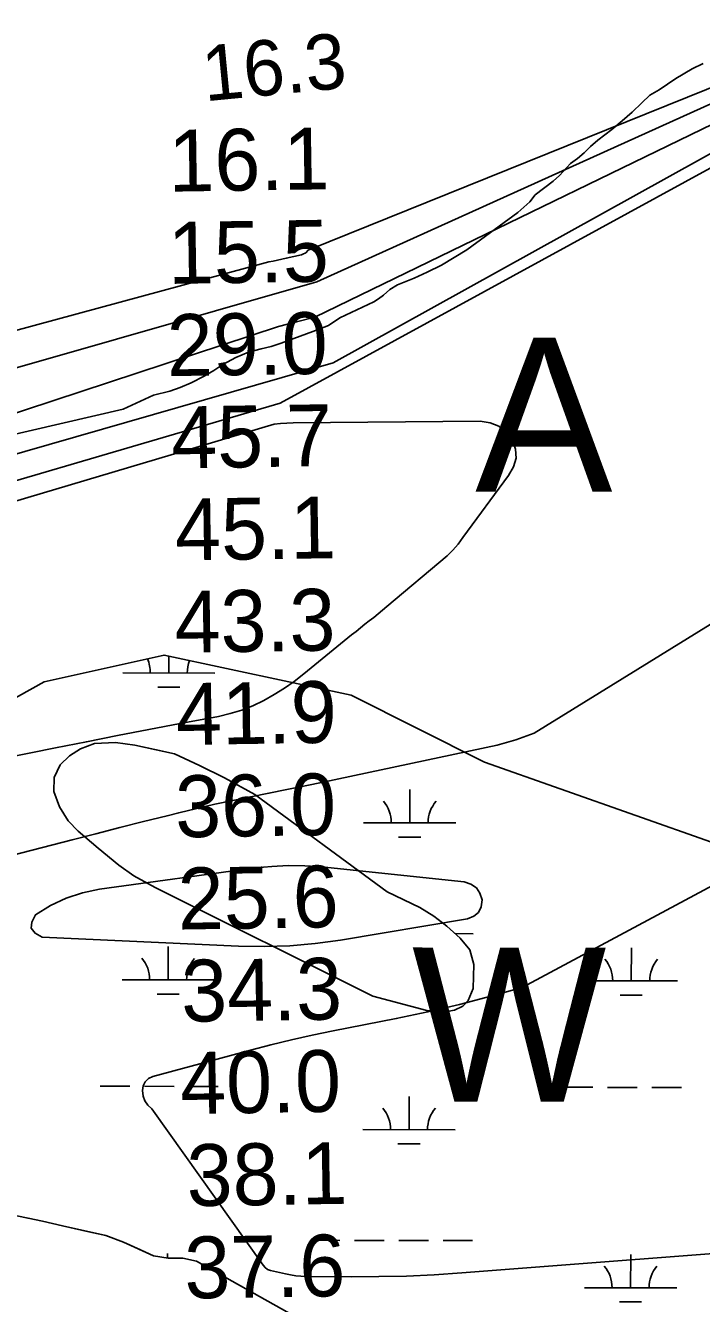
# Model space of a CAD drawing. Extents: x 3219052 to 3256913, y 800770 to 826146.
# Drawn here: x 3231079 to 3231811, y 813685 to 815070 of the extents above; entities that cross this region are included whole.
import ezdxf

# ---------------------------------------------------------------- set-up
doc = ezdxf.new("R2010")
doc.units = 0
for name, color, linetype in [('V-RIVR-IDEN', 7, 'Continuous'), ('V-RIVR-RANG', 7, 'Continuous'), ('V-SITE-VEGE', 7, 'Continuous'), ('V-TOPO-DPTH', 7, 'Continuous'), ('V-TOPO-MAJR', 7, 'Continuous'), ('V-TOPO-MINR', 7, 'Continuous'), ('V-TOPO-SHOR', 7, 'Continuous'), ('V-WETL-SWMP', 7, 'Continuous')]:
    doc.layers.add(name, color=color, linetype=linetype)

msp = doc.modelspace()

# ---------------------------------------------------------------- linework, layer by layer
at = {"layer": 'V-SITE-VEGE'}
for points in [[(3231746.5, 814986.4), (3231755.4, 814994.8), (3231765.5, 815000.8), (3231783.5, 815013), (3231801.4, 815023.4), (3231813.1, 815029.3)], [(3231051.7, 814623.6), (3231184.3, 814654.4), (3231217.2, 814669.8), (3231235.1, 814673.9), (3231246.4, 814677.8), (3231258.2, 814683.1), (3231272.2, 814690.1), (3231282.9, 814696.5), (3231292.5, 814702.9), (3231306.7, 814710.5), (3231320.5, 814716.2), (3231334.2, 814719.7), (3231344.8, 814722.5), (3231355.7, 814726.1), (3231390, 814738.8), (3231407.1, 814745.3), (3231419.4, 814753.4), (3231456.3, 814770.7), (3231461.4, 814773.9), (3231466.5, 814778.2), (3231473.5, 814784.3), (3231481.9, 814789.2), (3231499.9, 814796.5), (3231514.1, 814803.1), (3231529.5, 814810.4), (3231557.1, 814827.3), (3231612.3, 814867.6), (3231625.3, 814879.4), (3231631.1, 814886.8), (3231650.4, 814901.8), (3231657.5, 814907.6), (3231669.5, 814920.8), (3231677, 814926.2), (3231684, 814932.4), (3231691.2, 814939.1), (3231699, 814946.2), (3231714, 814957.8), (3231725.2, 814967.2), (3231736.1, 814976.3), (3231746.5, 814986.4)], [(3231370.8, 813670.7), (3231263.9, 813730.8), (3231249, 813734.1), (3231233.3, 813734), (3231217.5, 813736.5), (3231184.8, 813751.3), (3231165.6, 813758.7), (3231118.7, 813769.3), (3231097, 813774.3), (3231081.4, 813777.3), (3230918.1, 813810.9)]]:
    msp.add_lwpolyline(points, dxfattribs=at)
msp.add_lwpolyline([(3231455.1, 814018.2), (3231513.8, 814002.7), (3231524.4, 814001.6), (3231533.4, 814001.2), (3231543.5, 814002.8), (3231552.6, 814007.4), (3231558.5, 814013.3), (3231563.8, 814026.6), (3231564.5, 814052.3), (3231560.2, 814068.5), (3231549.7, 814081), (3231535.2, 814094.1), (3231521.3, 814104.9), (3231506.1, 814114.2), (3231470.6, 814131.4), (3231327.2, 814236.6), (3231294.3, 814254.9), (3231267.3, 814268.2), (3231240, 814280.8), (3231197.3, 814290.1), (3231176, 814293.1), (3231153.5, 814292), (3231138.2, 814286.2), (3231126.4, 814278.7), (3231116.3, 814269), (3231109.6, 814255), (3231109.3, 814240.1), (3231115.6, 814223.4), (3231125, 814208.1), (3231135.8, 814197.1), (3231157.4, 814178.6), (3231179.7, 814160.3), (3231196.2, 814148.5), (3231219.1, 814136)], close=True, dxfattribs=at)
at = {"layer": 'V-TOPO-DPTH'}
msp.add_lwpolyline([(3229216.4, 814641), (3229973.1, 814420.4), (3229979.2, 814421), (3229985.2, 814421.8), (3229991.3, 814422.6), (3230023.5, 814427.6), (3230041.5, 814430.8), (3230672.1, 814632.5), (3231342.2, 814814.2), (3231347, 814815), (3231351.7, 814816), (3231356.4, 814817), (3231361.2, 814818), (3231377.7, 814821.9), (3231379.4, 814822.4), (3231382.5, 814824.1), (3231385, 814826.7), (3231968.2, 815062.1)], dxfattribs=at)
at = {"layer": 'V-TOPO-MAJR'}
for points in [[(3229239.8, 814015.9), (3230018.6, 814365.6), (3230054.4, 814372.1), (3230249.6, 814407.6), (3230321.4, 814421), (3230393.2, 814434.6), (3230464.8, 814448.7), (3230536.4, 814463.2), (3230638.5, 814484.1), (3230659, 814488.4), (3231412, 814704.6), (3231956.2, 815006.5), (3231977.2, 815008.9), (3231998.3, 815011.3), (3232019.3, 815013.7), (3232638.1, 815145.4), (3232645.8, 815145.8), (3232653.6, 815146.2), (3232661.3, 815146.5), (3232669.1, 815146.7), (3232929.4, 815153.5), (3233006.6, 815155.4), (3233083.7, 815157.2)], [(3231122.6, 814124.5), (3231105.8, 814116.3), (3231089.6, 814106.4), (3231085.4, 814098.5), (3231084.6, 814091.7), (3231089, 814086.4), (3231096.8, 814082.1), (3231309.4, 814072.4), (3231337.2, 814072), (3231365, 814072.8), (3231392.6, 814075.3), (3231420.1, 814079), (3231557.7, 814101.8), (3231564.5, 814104.8), (3231569.7, 814109), (3231572.4, 814115.1), (3231573.5, 814122.4), (3231571.1, 814129.7), (3231567.4, 814135.6), (3231561.5, 814139.4), (3231554.2, 814141.9), (3231399.6, 814158.2), (3231381.5, 814159.4), (3231363.5, 814159.8), (3231345.5, 814158.8), (3231327.5, 814157.1), (3231159, 814134.1), (3231140.5, 814130.2), (3231122.6, 814124.5)]]:
    msp.add_lwpolyline(points, dxfattribs=at)
at = {"layer": 'V-TOPO-MINR'}
for points in [[(3229272.3, 814142.3), (3229994.7, 814406), (3230009.2, 814408.3), (3230073.9, 814418.5), (3230120.6, 814426.7), (3230167.1, 814435.8), (3230213.3, 814446.4), (3230259.3, 814458), (3230329.7, 814476.9), (3230630.3, 814574), (3231394.5, 814792.5), (3231945.4, 815041.4), (3231978, 815045.1), (3232010.6, 815048.8), (3232612.4, 815170.6), (3232633.9, 815172.1), (3232655.5, 815173.5), (3232677, 815174.6), (3232698.5, 815175.7), (3233370.6, 815232.4)], [(3229216.4, 814641), (3229973.1, 814420.4), (3229979.2, 814421), (3229985.2, 814421.8), (3229991.3, 814422.6), (3230023.5, 814427.6), (3230041.5, 814430.8), (3230672.1, 814632.5), (3231342.2, 814814.2), (3231347, 814815), (3231351.7, 814816), (3231356.4, 814817), (3231361.2, 814818), (3231377.7, 814821.9), (3231379.4, 814822.4), (3231382.5, 814824.1), (3231385, 814826.7), (3231968.2, 815062.1)], [(3229228, 814067.2), (3230005.8, 814387.7), (3230030.2, 814391.8), (3230129.4, 814408.6), (3230203.2, 814421.7), (3230678.2, 814523.5), (3230683.5, 814524.8), (3230688.7, 814526.1), (3230707.2, 814530.8), (3230713.1, 814532.4), (3230718.9, 814534.2), (3230724.6, 814536.2), (3230730.2, 814538.4), (3230735.8, 814540.6), (3230741.4, 814542.9), (3231352.9, 814744.1), (3231372.5, 814749), (3231392.1, 814754.1), (3231947.6, 815023.6)], [(3230714.2, 814473.1), (3231354.6, 814660.8), (3231952.8, 814988)], [(3230702.1, 814445.9), (3231348.1, 814638.1), (3231354.9, 814638.9), (3231361.8, 814639.3), (3231368.8, 814639.6), (3231571.5, 814641.4), (3231582.2, 814639.7), (3231591.8, 814636), (3231599.7, 814629.5), (3231606.5, 814621), (3231609.7, 814611), (3231610.5, 814601.2), (3231607.6, 814591.8), (3231602.3, 814582.7), (3231552.5, 814515.5), (3231547.7, 814508.2), (3231541.9, 814501.6), (3231535.5, 814495.5), (3231470.4, 814440.5), (3231465.7, 814436.5), (3231460.9, 814432.6), (3231456.1, 814428.8), (3231451.3, 814425), (3231446.5, 814421.3), (3231441.6, 814417.5), (3231436.9, 814413.6), (3231432.1, 814409.8), (3231380.4, 814367.4), (3231370, 814359.4), (3231359.4, 814351.9), (3231348.3, 814345), (3231336.9, 814338.5), (3231325.1, 814332.9), (3231313.1, 814328.1), (3231300.6, 814324.4), (3231287.9, 814321.4), (3231246.1, 814313.6), (3231212.3, 814307.1), (3231178.5, 814300.7)], [(3231891.5, 814464.6), (3231629.8, 814303.1), (3231610.1, 814295.9), (3231589.7, 814290.2), (3231401.1, 814250.2), (3231381.6, 814246.1), (3231362, 814242.1), (3231342.4, 814238.1), (3231322.8, 814234.3), (3231303.2, 814230.3), (3231283.7, 814226.2), (3231264.2, 814221.7), (3231244.8, 814217), (3231232.1, 814213.8), (3231206.4, 814207.3), (3231180.7, 814200.8), (3231155, 814194.2), (3231129.3, 814187.7), (3231019.6, 814159.5)], [(3231178.5, 814300.7), (3231144.7, 814294), (3231111, 814287.3), (3230912.6, 814247.4)], [(3231932.5, 813747.6), (3231551.6, 813718.1), (3231521.7, 813716.2), (3231491.7, 813714.7), (3231461.7, 813714.1), (3231431.6, 813713.9), (3231382.8, 813714.3), (3231377.2, 813714.6), (3231371.6, 813715), (3231366, 813715.9), (3231360.5, 813717), (3231344.2, 813720.7), (3231341, 813721.9), (3231338.3, 813723.9), (3231336.2, 813726.5), (3231215.4, 813895.9), (3231211.3, 813900), (3231208.1, 813904.6), (3231206.3, 813909.9), (3231205.3, 813915.7), (3231206.3, 813920.9), (3231208.3, 813925.4), (3231212, 813928.7), (3231216.7, 813931.1), (3231322.5, 813959.7), (3231344.7, 813965.5), (3231367.1, 813970.9), (3231389.5, 813975.9), (3231412.1, 813980.5), (3231480.4, 813993.9), (3231514.8, 814001.1), (3231549, 814009.1), (3231583, 814018), (3231616.8, 814027.6), (3231960.3, 814211.4)]]:
    msp.add_lwpolyline(points, dxfattribs=at)
at = {"layer": 'V-TOPO-SHOR'}
for points in [[(3231455.1, 814018.2), (3231219.1, 814136), (3231196.2, 814148.5), (3231179.7, 814160.3), (3231157.4, 814178.6), (3231135.8, 814197.1), (3231125, 814208.1), (3231115.6, 814223.4), (3231109.3, 814240.1), (3231109.6, 814255), (3231116.3, 814269), (3231126.4, 814278.7), (3231138.2, 814286.2), (3231153.5, 814292), (3231176, 814293.1), (3231197.3, 814290.1), (3231218.7, 814285.4), (3231240, 814280.8), (3231267.3, 814268.2), (3231294.3, 814254.9), (3231327.2, 814236.6), (3231470.6, 814131.4), (3231506.1, 814114.2), (3231521.3, 814104.9), (3231535.2, 814094.1), (3231549.7, 814081), (3231560.2, 814068.5), (3231564.5, 814052.3), (3231563.8, 814026.6), (3231558.5, 814013.3), (3231552.6, 814007.4), (3231543.5, 814002.8), (3231533.4, 814001.2), (3231524.4, 814001.6), (3231513.8, 814002.7), (3231455.1, 814018.2)], [(3230918.1, 813810.9), (3231081.4, 813777.3), (3231097, 813774.3), (3231118.7, 813769.3), (3231144.1, 813763.5), (3231165.6, 813758.7), (3231184.8, 813751.3), (3231203.1, 813743), (3231217.5, 813736.5), (3231233.3, 813734), (3231249, 813734.1), (3231263.9, 813730.8), (3231370.8, 813670.7)]]:
    msp.add_lwpolyline(points, dxfattribs=at)
at = {"layer": 'V-WETL-SWMP'}
for p, q in [((3231234, 814368.4), (3231234, 814386.7)), ((3231184, 814368.5), (3231284, 814368.3)), ((3231221.9, 814353), (3231245.9, 814353)), ((3231495.1, 814206), (3231495.1, 814242)), ((3231445.1, 814206.1), (3231545.1, 814205.9)), ((3231483, 814190.6), (3231507, 814190.6)), ((3231544.3, 814085.9), (3231564, 814085.8)), ((3231233.3, 814035.8), (3231233.3, 814071.8)), ((3231735.2, 814034.7), (3231735.3, 814070.7)), ((3231183.3, 814035.9), (3231283.3, 814035.7)), ((3231685.2, 814034.8), (3231785.2, 814034.6)), ((3231221.2, 814020.4), (3231245.2, 814020.3)), ((3231723.1, 814019.3), (3231747.1, 814019.3)), ((3231159.6, 813920.5), (3231191.6, 813920.4)), ((3231207.6, 813920.4), (3231239.6, 813920.3)), ((3231255.6, 813920.3), (3231287.6, 813920.2)), ((3231661.5, 813919.4), (3231693.5, 813919.4)), ((3231709.5, 813919.3), (3231741.5, 813919.3)), ((3231757.5, 813919.2), (3231789.5, 813919.2)), ((3231494.4, 813873.4), (3231494.4, 813909.4)), ((3231444.4, 813873.5), (3231544.4, 813873.3)), ((3231482.3, 813857.9), (3231506.3, 813857.9)), ((3231387.3, 813753.5), (3231419.3, 813753.4)), ((3231435.3, 813753.4), (3231467.3, 813753.3)), ((3231483.3, 813753.3), (3231515.3, 813753.2)), ((3231531.3, 813753.2), (3231563.3, 813753.1)), ((3231232.6, 813734.1), (3231232.6, 813739.1)), ((3231734.5, 813702), (3231734.6, 813738)), ((3231684.5, 813702.1), (3231784.5, 813701.9)), ((3231722.4, 813686.6), (3231746.4, 813686.6))]:
    msp.add_line(p, q, dxfattribs=at)
for points in [[(3229695, 813721.5), (3229796.3, 813837.4), (3229906.2, 813874.1), (3230013.4, 813909.8), (3230288.3, 813982.2), (3230476.4, 814011.2), (3230751.4, 814069.1), (3230925, 814098.1), (3230997.4, 814185), (3230968.4, 814286.4), (3231098.7, 814358.8), (3231228.9, 814387.8), (3231431.5, 814344.3), (3231576.2, 814271.9), (3231822.2, 814185), (3232097.1, 814141.6), (3232299.7, 814185), (3232473.4, 814257.4), (3232589.1, 814286.4), (3233211.4, 813982.2)], [(3231370.8, 813670.7), (3231263.9, 813730.8), (3231249, 813734.1), (3231233.3, 813734), (3231217.5, 813736.5), (3231203.1, 813743), (3231184.8, 813751.3), (3231165.6, 813758.7), (3231144.1, 813763.5), (3231118.7, 813769.3), (3231097, 813774.3), (3231081.4, 813777.3), (3230918.1, 813810.9)]]:
    msp.add_lwpolyline(points, dxfattribs=at)
msp.add_lwpolyline([(3231533.4, 814001.2), (3231543.5, 814002.8), (3231552.6, 814007.4), (3231558.5, 814013.3), (3231563.8, 814026.6), (3231564.5, 814052.3), (3231560.2, 814068.5), (3231549.7, 814081), (3231535.2, 814094.1), (3231521.3, 814104.9), (3231506.1, 814114.2), (3231470.6, 814131.4), (3231327.2, 814236.6), (3231294.3, 814254.9), (3231267.3, 814268.2), (3231240, 814280.8), (3231218.7, 814285.4), (3231197.3, 814290.1), (3231176, 814293.1), (3231153.5, 814292), (3231138.2, 814286.2), (3231126.4, 814278.7), (3231116.3, 814269), (3231109.6, 814255), (3231109.3, 814240.1), (3231115.6, 814223.4), (3231125, 814208.1), (3231135.8, 814197.1), (3231157.4, 814178.6), (3231179.7, 814160.3), (3231196.2, 814148.5), (3231219.1, 814136), (3231455.1, 814018.2), (3231513.8, 814002.7), (3231524.4, 814001.6)], close=True, dxfattribs=at)
for centre, start, end in [((3231178.7, 814369), 359.1081, 24.6577), ((3231289.2, 814368.8), 158.2519, 180.6517), ((3231439.8, 814206.6), 359.1081, 40.6518), ((3231550.3, 814206.4), 139.1081, 180.6517), ((3231178, 814036.4), 359.1081, 40.6518), ((3231288.5, 814036.1), 139.1081, 180.6517), ((3231679.9, 814035.3), 359.1081, 40.6518), ((3231790.4, 814035.1), 139.1081, 180.6517), ((3231439.1, 813873.9), 359.1081, 40.6518), ((3231549.6, 813873.7), 139.1081, 180.6517), ((3231679.2, 813702.6), 359.1081, 40.6518), ((3231789.7, 813702.4), 139.1081, 180.6517)]:
    msp.add_arc(centre, 35.2, start, end, dxfattribs=at)

# ---------------------------------------------------------------- texts
at = {"layer": 'V-RIVR-IDEN'}
for s, p in [('A', (3231566, 814565.1)), ('W', (3231497.3, 813903.9))]:
    msp.add_text(s, height=167, rotation=359.9463, dxfattribs=at).set_placement(p)
at = {"layer": 'V-RIVR-RANG'}
for s, height, rotation, p in [('16.3', 60, 5.5051, (3231273, 814988.1)), ('16.1', 67, 0.8883, (3231234, 814890.2)), ('15.5', 67, 0.8883, (3231233.4, 814790.2)), ('29.0', 67, 0.8883, (3231232.3, 814690.2)), ('45.7', 67, 0.8883, (3231237, 814590.2)), ('45.1', 67, 0.8883, (3231241.2, 814490.3)), ('43.3', 67, 0.8883, (3231240.6, 814390.3)), ('41.9', 67, 0.8883, (3231242.1, 814290.3)), ('36.0', 67, 0.8883, (3231241.3, 814190.2)), ('25.6', 67, 0.8883, (3231244.1, 814090.3)), ('34.3', 67, 0.8883, (3231247.8, 813990.3)), ('40.0', 67, 0.8883, (3231246.7, 813890.3)), ('38.1', 67, 0.8883, (3231253.7, 813790.4)), ('37.6', 67, 0.8883, (3231251.3, 813690.3))]:
    msp.add_text(s, height=height, rotation=rotation, dxfattribs=at).set_placement(p)

doc.saveas('drawing.dxf')
